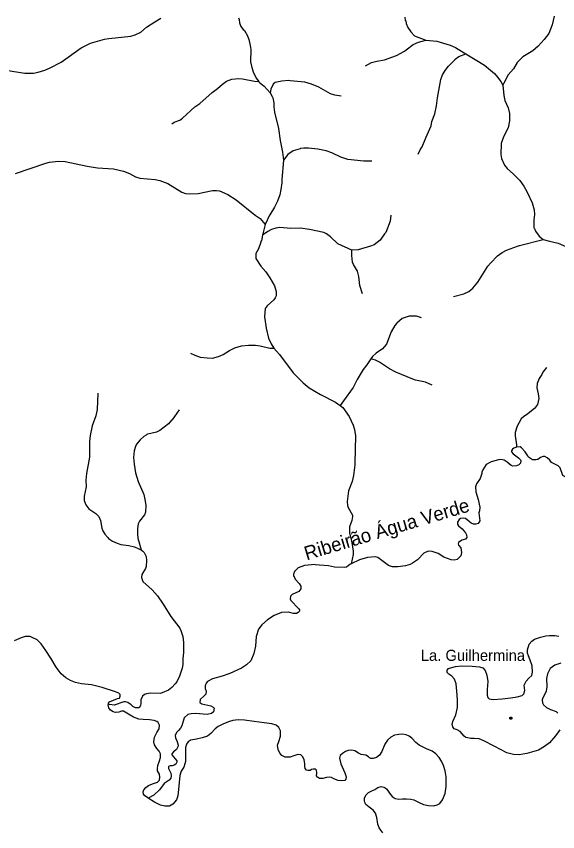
# Model space of a CAD drawing. Extents: x 396 to 422.2, y 7649.8 to 7677.6.
# Drawn here: x 416.15 to 420.08, y 7671.72 to 7677.63 of the extents above; entities that cross this region are included whole.
import ezdxf
from ezdxf.enums import TextEntityAlignment as Align

# ---------------------------------------------------------------- set-up
doc = ezdxf.new("R2010")
doc.units = 0
doc.header["$LTSCALE"] = 0.032
doc.header["$PDMODE"] = 32
doc.header["$PDSIZE"] = 0.016
doc.linetypes.add('LONG_DASHED', pattern=[7.5, 6, -1.5])
for name, color, linetype, lineweight in [('2', 7, 'Continuous', 25), ('3', 7, 'LONG_DASHED', 25), ('7', 7, 'Continuous', 25)]:
    doc.layers.add(name, color=color, linetype=linetype, lineweight=lineweight)
doc.layers.add('61', color=7, linetype='Continuous')

msp = doc.modelspace()

# ---------------------------------------------------------------- linework, layer by layer
at = {"layer": '2'}
for points in [[(416.8201, 7672.6418), (416.8222, 7672.6556), (416.8301, 7672.6664), (416.8881, 7672.69), (416.9018, 7672.693), (416.9077, 7672.7058), (416.9058, 7672.7176), (416.8969, 7672.7274), (416.8733, 7672.7382), (416.776, 7672.7697), (416.6983, 7672.7884), (416.6255, 7672.7952), (416.5832, 7672.8051), (416.5459, 7672.8188), (416.5134, 7672.8395), (416.479, 7672.869), (416.4426, 7672.9162), (416.4043, 7672.9821), (416.3689, 7673.0381), (416.3335, 7673.0853), (416.306, 7673.1138), (416.2696, 7673.1325), (416.2558, 7673.1384), (416.2194, 7673.1384), (416.1889, 7673.1296), (416.1398, 7673.1069)], [(417.1045, 7671.9716), (417.0847, 7671.984), (417.0759, 7671.9958), (417.0729, 7672.0125), (417.0778, 7672.0283), (417.0936, 7672.046), (417.1123, 7672.0588), (417.1418, 7672.0725), (417.1781, 7672.0843), (417.1909, 7672.0981), (417.1949, 7672.1197), (417.1929, 7672.1413), (417.1781, 7672.1659), (417.1762, 7672.1797), (417.1801, 7672.2053), (417.1919, 7672.2377), (417.1988, 7672.2633), (417.1978, 7672.2898), (417.189, 7672.3085), (417.1713, 7672.3272), (417.1565, 7672.3528), (417.1496, 7672.3754), (417.1545, 7672.4088), (417.1732, 7672.4442), (417.1899, 7672.4708), (417.1909, 7672.4973), (417.1821, 7672.515), (417.1722, 7672.5229), (417.1526, 7672.5307), (417.1182, 7672.5356), (417.0729, 7672.5376), (417.0415, 7672.5406), (417.0041, 7672.5543), (416.9441, 7672.5897), (416.9303, 7672.5986), (416.9156, 7672.5986), (416.8959, 7672.5917), (416.8723, 7672.5887), (416.8556, 7672.5927), (416.8379, 7672.6055), (416.8242, 7672.6222), (416.8201, 7672.6418)], [(419.1939, 7672.2888), (419.1673, 7672.3075), (419.1251, 7672.3242), (419.0739, 7672.3508), (419.0484, 7672.3714), (419.0199, 7672.4029), (419.0002, 7672.4177), (418.9786, 7672.4255), (418.951, 7672.4304), (418.9245, 7672.4285), (418.895, 7672.4236), (418.8665, 7672.4098), (418.8429, 7672.3882), (418.8242, 7672.3587), (418.8016, 7672.3046), (418.7858, 7672.278), (418.7632, 7672.2623), (418.7396, 7672.2544), (418.7239, 7672.2554), (418.7131, 7672.2603), (418.7052, 7672.2672), (418.6855, 7672.28), (418.6708, 7672.282), (418.6521, 7672.2839), (418.6344, 7672.2938), (418.6069, 7672.3115), (418.5843, 7672.3154), (418.5597, 7672.3134), (418.54, 7672.3065), (418.5164, 7672.2918), (418.5007, 7672.277), (418.4948, 7672.2574), (418.5056, 7672.2171), (418.5341, 7672.1502), (418.5439, 7672.1227), (418.542, 7672.105), (418.5341, 7672.0961), (418.5125, 7672.0932), (418.4869, 7672.0961), (418.4554, 7672.1069), (418.4377, 7672.1168), (418.421, 7672.1187), (418.4014, 7672.1168), (418.3758, 7672.1089), (418.3512, 7672.1109), (418.3374, 7672.1187), (418.3296, 7672.1305), (418.3315, 7672.1522), (418.3286, 7672.1699), (418.3227, 7672.1777), (418.305, 7672.1787), (418.2932, 7672.1758), (418.2824, 7672.1689), (418.2657, 7672.1679), (418.2558, 7672.1699), (418.248, 7672.1817), (418.244, 7672.1984), (418.244, 7672.219), (418.2391, 7672.2446), (418.2303, 7672.2682), (418.2145, 7672.282), (418.1939, 7672.2829), (418.1654, 7672.2751), (418.1378, 7672.2652), (418.1015, 7672.2652), (418.0788, 7672.2761), (418.0631, 7672.2947), (418.0523, 7672.3203), (418.0474, 7672.3508), (418.0552, 7672.3773), (418.068, 7672.4157), (418.068, 7672.456), (418.0562, 7672.4806), (418.0366, 7672.4953), (418.0051, 7672.5052), (417.951, 7672.513), (417.8773, 7672.5219), (417.8065, 7672.5337), (417.7622, 7672.5347), (417.7239, 7672.5307), (417.6993, 7672.5219), (417.655, 7672.5071), (417.6167, 7672.4865), (417.5951, 7672.4708), (417.5646, 7672.4354), (417.539, 7672.4157), (417.5016, 7672.4039), (417.4594, 7672.396), (417.4318, 7672.3911), (417.4175, 7672.3866), (417.4131, 7672.3852), (417.3994, 7672.3764), (417.3876, 7672.3596), (417.3807, 7672.3351), (417.3807, 7672.2938)], [(417.3807, 7672.2938), (417.3797, 7672.2338), (417.3758, 7672.2171), (417.3679, 7672.1925), (417.3492, 7672.163), (417.3394, 7672.1325)], [(419.2676, 7672.1227), (419.2617, 7672.1659), (419.249, 7672.2033), (419.2352, 7672.2348), (419.2175, 7672.2623), (419.1939, 7672.2888)], [(417.3394, 7672.1325), (417.3286, 7672.0293), (417.3237, 7671.984), (417.3148, 7671.9545), (417.2883, 7671.9231), (417.2637, 7671.9103), (417.2312, 7671.9093), (417.1978, 7671.9172), (417.1555, 7671.9398), (417.1098, 7671.9683), (417.1045, 7671.9716)], [(418.8094, 7671.7175), (418.7947, 7671.7362), (418.7829, 7671.752), (418.774, 7671.7785), (418.7652, 7671.8277), (418.7573, 7671.8601), (418.7386, 7671.8818), (418.7101, 7671.9014), (418.6875, 7671.9221), (418.6786, 7671.9358), (418.6757, 7671.9506), (418.6767, 7671.9683), (418.6855, 7671.9889), (418.7052, 7672.0086), (418.7298, 7672.0204), (418.7524, 7672.0302), (418.774, 7672.046), (418.7986, 7672.0519), (418.8163, 7672.047), (418.8271, 7672.042), (418.8389, 7672.0322), (418.8586, 7672.0047), (418.8763, 7671.9801), (418.8999, 7671.9644), (418.9245, 7671.9594), (418.953, 7671.9624), (418.9815, 7671.9634), (419.012, 7671.9604), (419.0346, 7671.9545), (419.0671, 7671.9388), (419.1054, 7671.9211), (419.1408, 7671.9152), (419.1782, 7671.9132), (419.2027, 7671.9191), (419.2224, 7671.9299), (419.2421, 7671.9555), (419.2617, 7672.0017), (419.2676, 7672.0529), (419.2676, 7672.1227)]]:
    msp.add_lwpolyline(points, dxfattribs=at)
at = {"layer": '3'}
for points in [[(419.2931, 7672.9081), (419.3351, 7672.9213), (419.383, 7672.9261), (419.4562, 7672.9249), (419.5089, 7672.9189), (419.5353, 7672.9105), (419.5521, 7672.8913), (419.5641, 7672.8577), (419.5701, 7672.8133), (419.5665, 7672.7546), (419.5653, 7672.7138), (419.5701, 7672.697), (419.5797, 7672.6862), (419.6085, 7672.6826), (419.6732, 7672.6874), (419.738, 7672.6934), (419.7824, 7672.7006), (419.8183, 7672.7102), (419.8315, 7672.7222), (419.8375, 7672.7486), (419.8327, 7672.7869), (419.8483, 7672.8157), (419.8663, 7672.8373), (419.8891, 7672.8565), (419.8951, 7672.8805), (419.8915, 7672.9273), (419.8783, 7672.9668), (419.8639, 7672.9992), (419.8567, 7673.0184), (419.8567, 7673.0412), (419.8687, 7673.082), (419.8903, 7673.1059), (419.9083, 7673.1203), (419.9515, 7673.1347), (419.9898, 7673.1443), (420.0174, 7673.1455), (420.0558, 7673.1467), (420.0846, 7673.1419)], [(419.3099, 7672.8517), (419.2883, 7672.8649), (419.2763, 7672.8769), (419.2763, 7672.8937), (419.2859, 7672.9057), (419.2931, 7672.9081)], [(420.099, 7672.9464), (420.0558, 7672.9309), (420.0222, 7672.9057), (420.0018, 7672.8685), (419.9946, 7672.8349), (419.997, 7672.775), (419.9934, 7672.7438), (419.9838, 7672.721), (419.9683, 7672.6946), (419.9635, 7672.6802), (419.9659, 7672.6586), (419.9731, 7672.643), (419.9958, 7672.625), (420.0246, 7672.6107), (420.0654, 7672.5951), (420.0786, 7672.5831)], [(420.0918, 7672.4632), (420.0618, 7672.42), (420.0174, 7672.3696), (419.9814, 7672.3408), (419.9371, 7672.3156), (419.8531, 7672.2905), (419.7968, 7672.2809), (419.7572, 7672.2833), (419.7092, 7672.2965), (419.6169, 7672.3432), (419.5425, 7672.384), (419.5065, 7672.3984), (419.4706, 7672.4008), (419.4466, 7672.4008), (419.4118, 7672.4068), (419.3986, 7672.4176), (419.3698, 7672.4512), (419.3482, 7672.462), (419.3267, 7672.4703), (419.3159, 7672.4835), (419.3123, 7672.5003), (419.3171, 7672.5219), (419.3387, 7672.5723), (419.3518, 7672.6238), (419.3518, 7672.679), (419.347, 7672.7426), (419.3399, 7672.7953), (419.3279, 7672.8289), (419.3099, 7672.8517)]]:
    msp.add_lwpolyline(points, dxfattribs=at)
msp.add_point((419.7372, 7672.5474), dxfattribs=at)
at = {"layer": '7'}
for points in [[(420.0509, 7677.6304), (420.0361, 7677.5681), (420.012, 7677.5066), (419.9782, 7677.4624), (419.9354, 7677.4148), (419.8963, 7677.3799), (419.825, 7677.3372), (419.7822, 7677.296), (419.7574, 7677.2507), (419.7183, 7677.2055), (419.686, 7677.1464), (419.6784, 7677.132)], [(415.7672, 7677.452), (415.7897, 7677.4139), (415.8228, 7677.3721), (415.9126, 7677.2952), (415.9574, 7677.2677), (416.0292, 7677.247), (416.2163, 7677.2191), (416.2796, 7677.2196), (416.3126, 7677.2262), (416.3605, 7677.2407), (416.3938, 7677.2542), (416.48, 7677.2982), (416.6248, 7677.4015), (416.6919, 7677.4357), (416.7928, 7677.4644), (416.8255, 7677.4701), (416.9846, 7677.4868), (417.0159, 7677.4951), (417.0554, 7677.5165), (417.0971, 7677.5507), (417.1577, 7677.5912), (417.202, 7677.6164)], [(417.7651, 7677.6193), (417.7696, 7677.6084), (417.7725, 7677.5831), (417.7813, 7677.5572), (417.7985, 7677.534), (417.8066, 7677.5277), (417.8285, 7677.4895), (417.8396, 7677.4613), (417.8493, 7677.4182), (417.8526, 7677.3895), (417.8511, 7677.3007), (417.8602, 7677.2592), (417.8704, 7677.2285), (417.8923, 7677.1833), (417.9112, 7677.1573)], [(418.9689, 7677.6252), (418.9719, 7677.6), (418.9753, 7677.5976), (418.9789, 7677.5794), (418.9911, 7677.549), (419.0119, 7677.5174), (419.0387, 7677.4897), (419.1202, 7677.4567), (419.1216, 7677.4566)], [(418.6842, 7677.2708), (418.7277, 7677.295), (418.7658, 7677.3057), (418.8226, 7677.3143), (418.9098, 7677.3456), (418.9666, 7677.3769), (418.9788, 7677.3865), (419.0284, 7677.4258), (419.0689, 7677.4443), (419.1216, 7677.4566)], [(419.1216, 7677.4566), (419.2, 7677.4503), (419.298, 7677.4205), (419.3356, 7677.4041), (419.3558, 7677.3919), (419.4099, 7677.3591)], [(419.0667, 7676.6308), (419.0833, 7676.669), (419.0955, 7676.6845), (419.1203, 7676.75), (419.1588, 7676.8382), (419.1655, 7676.8679), (419.1859, 7676.9243), (419.1986, 7676.9813), (419.2052, 7677.0398), (419.2303, 7677.1737), (419.2431, 7677.2062), (419.2617, 7677.2376), (419.2847, 7677.2689), (419.3328, 7677.3178), (419.3349, 7677.3199), (419.3614, 7677.3401), (419.4099, 7677.3591)], [(419.4099, 7677.3591), (419.5468, 7677.2761), (419.6188, 7677.216), (419.6412, 7677.1906), (419.6639, 7677.1588), (419.6784, 7677.132)], [(417.2806, 7676.8518), (417.2975, 7676.8627), (417.3385, 7676.8789), (417.3579, 7676.8917), (417.4488, 7676.9746), (417.4833, 7676.9997), (417.5725, 7677.0774), (417.612, 7677.1068), (417.6471, 7677.1394), (417.6779, 7677.1606), (417.7158, 7677.1743), (417.7635, 7677.1791), (417.7924, 7677.1766), (417.881, 7677.1599), (417.9112, 7677.1573)], [(417.9112, 7677.1573), (417.9132, 7677.1545), (417.9498, 7677.1244), (417.9943, 7677.0755)], [(418.5084, 7677.0523), (418.4616, 7677.0595), (418.4312, 7677.0679), (418.3459, 7677.1178), (418.2941, 7677.1392), (418.244, 7677.1534), (418.1372, 7677.1639), (418.1297, 7677.1646), (418.0787, 7677.1616), (418.0308, 7677.15), (418.0153, 7677.1382), (417.9979, 7677.1033), (417.9943, 7677.0755)], [(419.6784, 7677.132), (419.6853, 7677.0567), (419.6945, 7677.0199), (419.7171, 7676.9677), (419.7268, 7676.9265), (419.7267, 7676.8744), (419.7181, 7676.8232), (419.6835, 7676.7584), (419.6678, 7676.7081), (419.6646, 7676.6292), (419.6687, 7676.6014), (419.692, 7676.553), (419.7112, 7676.5285), (419.7565, 7676.4882), (419.8011, 7676.4403), (419.8306, 7676.3996), (419.8558, 7676.3571), (419.891, 7676.2802), (419.9068, 7676.2299), (419.9094, 7676.1938), (419.9039, 7676.1568), (419.9047, 7676.0975), (419.9085, 7676.0941), (419.9148, 7676.075), (419.9418, 7676.0381), (419.9723, 7676.0151)], [(417.9943, 7677.0755), (418.0082, 7677.0501), (418.0137, 7677.0399), (418.02, 7677.0043), (418.0201, 7676.9753), (418.0256, 7676.9372), (418.055, 7676.8185), (418.0648, 7676.7313), (418.0838, 7676.6458), (418.091, 7676.5875)], [(418.7306, 7676.5812), (418.6721, 7676.5812), (418.5573, 7676.5945), (418.5059, 7676.6099), (418.4406, 7676.6406), (418.3993, 7676.6555), (418.3379, 7676.6678), (418.2723, 7676.6751), (418.2363, 7676.675), (418.2125, 7676.6719), (418.2107, 7676.6717), (418.1611, 7676.6569), (418.1226, 7676.63), (418.091, 7676.5875)], [(416.1489, 7676.4909), (416.3673, 7676.5669), (416.3956, 7676.5736), (416.4598, 7676.5824), (416.5083, 7676.5785), (416.6672, 7676.5459), (416.7418, 7676.5339), (416.8596, 7676.5257), (416.93, 7676.5086), (416.9734, 7676.4909), (417.0181, 7676.4686), (417.0496, 7676.459), (417.1597, 7676.4481), (417.1935, 7676.4414), (417.2526, 7676.4192), (417.3526, 7676.3564), (417.3808, 7676.3475), (417.4062, 7676.3442), (417.4728, 7676.3475), (417.5763, 7676.3695), (417.6058, 7676.3695), (417.6269, 7676.3655), (417.6857, 7676.3389), (417.7469, 7676.3009), (417.8856, 7676.1899), (417.9204, 7676.1654), (417.9577, 7676.1226)], [(418.091, 7676.5875), (418.0783, 7676.4493), (418.0783, 7676.4235), (418.0719, 7676.3756), (418.0633, 7676.3383), (418.0461, 7676.2907), (418.025, 7676.2486), (417.9901, 7676.1924), (417.9885, 7676.189), (417.9577, 7676.1226)], [(418.8667, 7676.1912), (418.863, 7676.1462), (418.832, 7676.0653), (418.8208, 7676.0545), (418.7914, 7676.0102), (418.7461, 7675.975), (418.7207, 7675.9645), (418.6313, 7675.939), (418.5841, 7675.9374)], [(417.9577, 7676.1226), (417.94, 7676.055), (417.9383, 7676.0461)], [(418.5841, 7675.9374), (418.4827, 7675.9835), (418.4302, 7676.0328), (418.4012, 7676.0545), (418.3818, 7676.0634), (418.2776, 7676.0871), (418.2138, 7676.0952), (418.1441, 7676.0938), (418.0647, 7676.1009), (418.0336, 7676.0962), (418.0038, 7676.0863), (417.9993, 7676.0842), (417.9757, 7676.073), (417.9383, 7676.0461)], [(417.9383, 7676.0461), (417.9305, 7676.0054), (417.9276, 7676.0039), (417.9239, 7675.987), (417.9078, 7675.9456), (417.8891, 7675.913), (417.8894, 7675.8765), (417.9254, 7675.8215), (417.9624, 7675.7797), (417.992, 7675.7366), (418.0247, 7675.6792), (418.0376, 7675.6362), (418.0361, 7675.6059), (418.0304, 7675.5912), (418.0206, 7675.5766), (417.9729, 7675.5346), (417.9575, 7675.5149), (417.9524, 7675.4542), (417.9635, 7675.3724), (417.9821, 7675.3002), (418.0011, 7675.2575), (418.0192, 7675.2271)], [(419.3219, 7675.6012), (419.3961, 7675.6212), (419.4335, 7675.6384), (419.4625, 7675.6603), (419.4991, 7675.7051), (419.5716, 7675.8203), (419.5887, 7675.8422), (419.6412, 7675.8956), (419.6731, 7675.9201), (419.7051, 7675.9376), (419.7865, 7675.9662), (419.8007, 7675.97), (419.9723, 7676.0151)], [(419.9723, 7676.0151), (420.0175, 7676.0007), (420.0796, 7675.9866), (420.1742, 7675.9456), (420.2235, 7675.9323), (420.2539, 7675.9193), (420.2757, 7675.8939), (420.2762, 7675.8932)], [(418.662, 7675.62), (418.644, 7675.6808), (418.6349, 7675.7463), (418.6262, 7675.7839), (418.5971, 7675.8335), (418.5904, 7675.8506), (418.5851, 7675.8976), (418.5841, 7675.9374)], [(419.0909, 7675.4476), (419.0525, 7675.4596), (419.0019, 7675.4579), (419.0017, 7675.4578), (418.9501, 7675.4427), (418.9114, 7675.4091), (418.8956, 7675.3915), (418.8699, 7675.3449), (418.8369, 7675.2565), (418.807, 7675.2225), (418.7623, 7675.1909), (418.7347, 7675.1677), (418.7232, 7675.1504)], [(417.417, 7675.19), (417.4478, 7675.1754), (417.4861, 7675.1624), (417.5365, 7675.1559), (417.5757, 7675.1542), (417.6197, 7675.1653), (417.6526, 7675.1809), (417.6987, 7675.2108), (417.7374, 7675.2298), (417.7853, 7675.2427), (417.8359, 7675.2482), (417.8881, 7675.2474), (417.9216, 7675.2435), (417.9901, 7675.2277), (418.0192, 7675.2271)], [(418.0192, 7675.2271), (418.0198, 7675.2261), (418.0389, 7675.2052), (418.0615, 7675.1805), (418.1594, 7675.0492), (418.2326, 7674.976), (418.2765, 7674.9397), (418.3581, 7674.8922), (418.4663, 7674.8361), (418.5002, 7674.8111)], [(418.7232, 7675.1504), (418.6938, 7675.1059), (418.6678, 7675.0729), (418.6237, 7674.9994), (418.5952, 7674.9423), (418.5255, 7674.846), (418.5002, 7674.8111)], [(419.1682, 7674.959), (419.1187, 7674.9796), (419.0459, 7674.9959), (419.0269, 7675.0035), (418.9034, 7675.0531), (418.8579, 7675.0767), (418.7861, 7675.1256), (418.7561, 7675.1396), (418.7232, 7675.1504)], [(419.9943, 7675.0878), (419.9677, 7675.0538), (419.9621, 7675.0364), (419.9421, 7675.0073), (419.9288, 7674.9721), (419.9262, 7674.9401), (419.9356, 7674.8958), (419.9388, 7674.863), (419.9309, 7674.8198), (419.9091, 7674.7895), (419.8508, 7674.7438), (419.8302, 7674.7312), (419.8115, 7674.7142), (419.7825, 7674.662), (419.7682, 7674.6154), (419.7682, 7674.5908), (419.7777, 7674.5273), (419.7769, 7674.511)], [(416.7461, 7674.9007), (416.7392, 7674.7834), (416.7295, 7674.7372), (416.7039, 7674.6648), (416.6883, 7674.5947), (416.6851, 7674.552), (416.6834, 7674.4364), (416.6627, 7674.3181), (416.658, 7674.2713), (416.6595, 7674.2236), (416.6461, 7674.1538), (416.6467, 7674.1238), (416.6581, 7674.0917), (416.6789, 7674.0638), (416.7308, 7674.0303), (416.7523, 7674.0067), (416.7633, 7673.9799), (416.774, 7673.9241), (416.7811, 7673.9039), (416.7949, 7673.88), (416.8173, 7673.8544), (416.822, 7673.849), (416.8504, 7673.8294), (416.8841, 7673.8139), (416.9119, 7673.8048), (416.9697, 7673.7967), (417.0117, 7673.7873), (417.0415, 7673.7743), (417.0585, 7673.7669)], [(418.5002, 7674.8111), (418.5202, 7674.7964), (418.5657, 7674.7312), (418.5953, 7674.6702), (418.6056, 7674.6383), (418.6118, 7674.5915), (418.6065, 7674.3942), (418.6062, 7674.3819), (418.5973, 7674.3049), (418.5884, 7674.26), (418.562, 7674.1927), (418.5513, 7674.1166), (418.5536, 7674.0875), (418.5583, 7674.0733), (418.5896, 7674.0181), (418.5902, 7674.007), (418.5852, 7673.9791), (418.5687, 7673.9337), (418.5673, 7673.8896), (418.5863, 7673.8195), (418.5947, 7673.757), (418.5958, 7673.7487), (418.5957, 7673.7323), (418.5803, 7673.6654)], [(417.3331, 7674.7802), (417.2835, 7674.7072), (417.2781, 7674.7046), (417.2575, 7674.6782), (417.1952, 7674.6306), (417.1691, 7674.6185), (417.1073, 7674.6033), (417.1037, 7674.6067), (417.0954, 7674.5973), (417.0774, 7674.5879), (417.0509, 7674.5638), (417.0261, 7674.5312), (417.017, 7674.5149), (417.0088, 7674.4824), (417.0041, 7674.4341), (417.0074, 7674.3856), (417.0181, 7674.3246), (417.0369, 7674.2622), (417.0773, 7674.1672), (417.0886, 7674.119), (417.0925, 7674.0875), (417.0903, 7674.04), (417.0838, 7674.0206), (417.047, 7673.9728), (417.0377, 7673.9535), (417.0312, 7673.9215), (417.0312, 7673.8747), (417.0369, 7673.8397), (417.0408, 7673.8264), (417.0538, 7673.7828), (417.0585, 7673.7669)], [(419.7769, 7674.511), (419.7587, 7674.5035), (419.7494, 7674.4959), (419.7428, 7674.4836), (419.7427, 7674.475), (419.753, 7674.4621), (419.7937, 7674.4332), (419.8062, 7674.4175), (419.8087, 7674.4104), (419.8063, 7674.3944), (419.7947, 7674.3829), (419.779, 7674.3742), (419.7514, 7674.3711), (419.7399, 7674.3759), (419.7102, 7674.4019), (419.6884, 7674.4149), (419.6645, 7674.4196), (419.647, 7674.418), (419.594, 7674.4028), (419.5592, 7674.3843), (419.5335, 7674.3455), (419.5275, 7674.3294), (419.528, 7674.3201), (419.5147, 7674.2837), (419.4889, 7674.2447), (419.4801, 7674.2234), (419.4827, 7674.1873), (419.4993, 7674.1309), (419.5114, 7674.0763), (419.5098, 7674.048), (419.5051, 7674.0352), (419.5122, 7673.9765), (419.5014, 7673.9571), (419.4843, 7673.9516), (419.4661, 7673.9524), (419.4489, 7673.9589), (419.4097, 7673.9923), (419.3946, 7673.9962), (419.3716, 7673.9936), (419.3631, 7673.9858), (419.3507, 7673.9664), (419.3504, 7673.9528), (419.3583, 7673.939), (419.3838, 7673.918), (419.4091, 7673.8904), (419.4156, 7673.876), (419.4171, 7673.8551), (419.4092, 7673.8439), (419.3823, 7673.8351), (419.3583, 7673.8203), (419.3557, 7673.8103), (419.3581, 7673.8009), (419.374, 7673.7812), (419.3803, 7673.7469), (419.3745, 7673.7219), (419.3476, 7673.6974), (419.3264, 7673.6916), (419.3047, 7673.6938), (419.252, 7673.714), (419.2096, 7673.7388), (419.1681, 7673.7538), (419.139, 7673.7561), (419.1073, 7673.7427), (419.0613, 7673.6937), (419.0256, 7673.6688), (419.0067, 7673.6602), (418.9737, 7673.6512), (418.9193, 7673.6429), (418.8789, 7673.643), (418.8498, 7673.6539), (418.7745, 7673.7107), (418.7553, 7673.7162), (418.6979, 7673.7115), (418.6402, 7673.6938), (418.5803, 7673.6654)], [(420.0194, 7674.4149), (420.0013, 7674.4322), (419.9844, 7674.4419), (419.9708, 7674.4411), (419.9521, 7674.435), (419.9316, 7674.4208), (419.9186, 7674.417), (419.8952, 7674.4183), (419.8656, 7674.4373), (419.8606, 7674.4459), (419.8542, 7674.4552), (419.8411, 7674.4753), (419.8152, 7674.5042), (419.8039, 7674.512), (419.7769, 7674.511)], [(420.2574, 7674.1724), (420.237, 7674.1884), (420.2006, 7674.2559), (420.169, 7674.2771), (420.1347, 7674.2914), (420.1142, 7674.3043), (420.095, 7674.3613), (420.0799, 7674.375), (420.0311, 7674.3986), (420.0194, 7674.4149)], [(417.0585, 7673.7669), (417.07, 7673.7565), (417.0801, 7673.7474), (417.0948, 7673.7174), (417.0981, 7673.6891), (417.0949, 7673.6453), (417.0913, 7673.6322), (417.064, 7673.5882), (417.0608, 7673.5658), (417.0713, 7673.5368), (417.1375, 7673.476), (417.1761, 7673.4342), (417.2191, 7673.3734), (417.2738, 7673.2829), (417.3386, 7673.1994), (417.3468, 7673.1815), (417.3597, 7673.1385), (417.3661, 7673.0963), (417.3661, 7673.0219), (417.3613, 7672.9802), (417.3605, 7672.9368), (417.3551, 7672.9092), (417.3357, 7672.8507), (417.3168, 7672.8114), (417.3062, 7672.7956), (417.2822, 7672.7694), (417.2563, 7672.7491), (417.2117, 7672.7294), (417.1954, 7672.7266), (417.1262, 7672.7274), (417.0978, 7672.7241), (417.0832, 7672.7174), (417.0679, 7672.7058), (417.0568, 7672.6787), (417.0568, 7672.6736), (417.0567, 7672.6533), (417.0536, 7672.6392), (417.0443, 7672.6214), (417.0182, 7672.6215), (416.9978, 7672.631), (416.9855, 7672.6439), (416.9617, 7672.6608), (416.9466, 7672.6651), (416.9323, 7672.6651), (416.8621, 7672.6421), (416.8327, 7672.645), (416.8201, 7672.6418)], [(418.5803, 7673.6654), (418.571, 7673.661), (418.5458, 7673.6412), (418.5308, 7673.6374), (418.4591, 7673.6413), (418.4157, 7673.6503), (418.3207, 7673.658), (418.3194, 7673.6611), (418.243, 7673.6531), (418.1966, 7673.6353), (418.1701, 7673.6086), (418.1637, 7673.5911), (418.1637, 7673.5756)], [(418.1637, 7673.5756), (418.1671, 7673.5728), (418.1737, 7673.5532), (418.2033, 7673.522), (418.2147, 7673.5027), (418.2162, 7673.4846), (418.2018, 7673.4635), (418.1519, 7673.4437), (418.14, 7673.4295), (418.1382, 7673.4117), (418.1431, 7673.4004), (418.1985, 7673.3417), (418.2051, 7673.3308), (418.2049, 7673.323), (418.1974, 7673.3129), (418.1831, 7673.3061), (418.1636, 7673.3048), (418.1271, 7673.3136), (418.0759, 7673.3127), (418.0229, 7673.2903), (417.9738, 7673.2585), (417.9329, 7673.2232), (417.9089, 7673.1914), (417.8917, 7673.1385), (417.8876, 7673.068), (417.8748, 7673.015), (417.8531, 7672.9616), (417.8211, 7672.9327), (417.7865, 7672.9089), (417.7009, 7672.8707), (417.6465, 7672.8509), (417.5763, 7672.8309), (417.5383, 7672.8132), (417.5289, 7672.8011), (417.5225, 7672.7814), (417.5235, 7672.762), (417.5295, 7672.7432), (417.5271, 7672.7218), (417.5186, 7672.7101), (417.4859, 7672.6811), (417.485, 7672.6608), (417.4993, 7672.6506), (417.5636, 7672.6365), (417.5798, 7672.6269), (417.5878, 7672.6186), (417.5822, 7672.5927), (417.5674, 7672.58), (417.5376, 7672.5744), (417.453, 7672.5806), (417.4203, 7672.579), (417.3972, 7672.5726), (417.371, 7672.5503), (417.3533, 7672.4906), (417.343, 7672.4746), (417.3288, 7672.4587), (417.3162, 7672.4445), (417.3064, 7672.4248), (417.3079, 7672.4016), (417.317, 7672.3842), (417.3269, 7672.351), (417.3243, 7672.3399), (417.3137, 7672.3196), (417.2922, 7672.3025), (417.2818, 7672.2898), (417.2816, 7672.2811), (417.3172, 7672.2372), (417.3181, 7672.2278), (417.3104, 7672.2141), (417.2982, 7672.207), (417.2832, 7672.2027), (417.2692, 7672.2026), (417.2579, 7672.1969), (417.2577, 7672.1831), (417.2727, 7672.148), (417.2768, 7672.1301), (417.2731, 7672.1132), (417.2618, 7672.0969), (417.2255, 7672.0732), (417.192, 7672.0278), (417.1498, 7671.9884), (417.1098, 7671.9683)]]:
    msp.add_lwpolyline(points, dxfattribs=at)

# ---------------------------------------------------------------- texts
at = {"layer": '61'}
msp.add_text('Ribeirão Água Verde', height=0.1, rotation=16.705, dxfattribs=at).set_placement((418.8519, 7673.8681), align=Align.CENTER)
msp.add_text('La. Guilhermina', height=0.08, dxfattribs=at).set_placement((419.8401, 7672.9621), align=Align.RIGHT)

doc.saveas('drawing.dxf')
